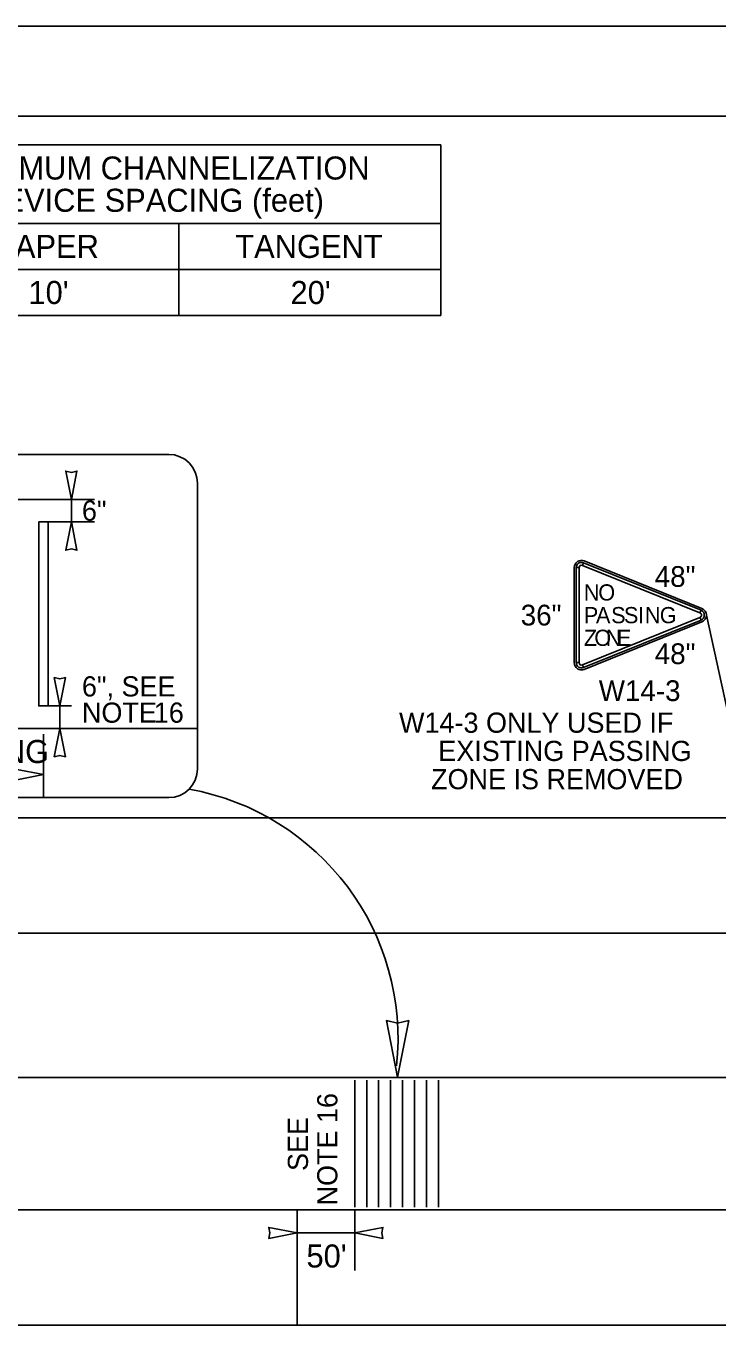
# Model space of a CAD drawing. Extents: x 99977 to 100176, y 99905 to 100011.
# Drawn here: x 100003.968 to 100006.368, y 99916.159 to 99920.687 of the extents above; entities that cross this region are included whole.
import ezdxf

# ---------------------------------------------------------------- set-up
doc = ezdxf.new("R2010")
doc.units = 0
for name, color, linetype in [('Default', 7, 'Continuous'), ('RD_ED_ShoulderPavedEdge', 7, 'Continuous'), ('RD_MK_LineEdgeWhite', 7, 'Continuous'), ('RD_MK_LineSkipCenter', 7, 'Continuous'), ('SH_GI_PlotLimits', 7, 'Continuous'), ('SH_GI_SheetBorder', 7, 'Continuous'), ('SH_TI_Tables', 7, 'Continuous'), ('TR_SN_ConstructionSigns', 7, 'Continuous'), ('TR_WZ_WorkZoneDetails', 7, 'Continuous'), ('TR_WZ_WorkZoneTextCurrent', 7, 'Continuous')]:
    doc.layers.add(name, color=color, linetype=linetype)

msp = doc.modelspace()

# ---------------------------------------------------------------- linework, layer by layer
at = {"layer": 'Default'}
for p, q in [((100005.8762, 99918.8083), (100005.886, 99918.8083)), ((100005.886, 99918.8083), (100005.8762, 99918.8083)), ((100005.8762, 99918.8083), (100005.8762, 99918.8083)), ((100005.8762, 99918.8083), (100005.886, 99918.8083)), ((100005.8976, 99918.8161), (100005.9013, 99918.8253)), ((100005.9013, 99918.8253), (100005.8976, 99918.8161)), ((100005.8976, 99918.8161), (100005.9013, 99918.8253))]:
    msp.add_line(p, q, dxfattribs=at)
for radius in [0.0183, 0.0183, 0.00844, 0.00844]:
    msp.add_arc((100005.8945, 99918.8083), radius, 67.9757, 180, dxfattribs=at)
at = {"layer": 'RD_ED_ShoulderPavedEdge'}
for p, q in [((100000.1076, 99917.9393), (100015.45, 99917.9393)), ((100000.1076, 99916.1793), (100015.45, 99916.1793))]:
    msp.add_line(p, q, dxfattribs=at)
at = {"layer": 'RD_MK_LineEdgeWhite'}
for p, q in [((100000.1076, 99917.5393), (100010.4406, 99917.5393)), ((100000.1076, 99916.5793), (100011.1899, 99916.5793))]:
    msp.add_line(p, q, dxfattribs=at)
at = {"layer": 'RD_MK_LineSkipCenter'}
msp.add_lwpolyline([(100006.4076, 99917.0393), (100001.2576, 99917.0393)], dxfattribs=at)
at = {"layer": 'SH_GI_PlotLimits'}
msp.add_lwpolyline([(99999.0625, 99909.6875), (100016.0625, 99909.6875), (100016.0625, 99920.6875), (99999.0625, 99920.6875)], close=True, dxfattribs=at)
at = {"layer": 'SH_GI_SheetBorder'}
msp.add_line((100000, 99920.375), (100015.75, 99920.375), dxfattribs=at)
at = {"layer": 'SH_TI_Tables'}
for p, q in [((100003.5886, 99920.275), (100005.4067, 99920.275)), ((100005.4067, 99919.683), (100005.4067, 99920.275)), ((100003.5886, 99920.003), (100005.4067, 99920.003)), ((100004.4977, 99919.683), (100004.4977, 99920.003)), ((100003.5886, 99919.843), (100004.4977, 99919.843)), ((100004.4977, 99919.843), (100005.4067, 99919.843)), ((100003.5886, 99919.683), (100005.4067, 99919.683))]:
    msp.add_line(p, q, dxfattribs=at)
at = {"layer": 'TR_SN_ConstructionSigns'}
for p, q in [((100005.8691, 99918.8083), (100005.8691, 99918.4784)), ((100005.8762, 99918.8083), (100005.8762, 99918.4784)), ((100005.8762, 99918.8083), (100005.8762, 99918.4784)), ((100005.886, 99918.8083), (100005.8762, 99918.8083)), ((100005.886, 99918.4784), (100005.886, 99918.8083)), ((100005.886, 99918.4784), (100005.886, 99918.8083)), ((100005.9013, 99918.8253), (100005.8976, 99918.8161)), ((100005.8976, 99918.8161), (100006.3054, 99918.6512)), ((100005.8976, 99918.8161), (100006.3054, 99918.6512)), ((100006.3091, 99918.6603), (100005.9013, 99918.8253)), ((100006.3091, 99918.6603), (100005.9013, 99918.8253)), ((100006.3117, 99918.6668), (100005.9039, 99918.8318)), ((100006.3054, 99918.6355), (100005.8976, 99918.4706)), ((100006.3054, 99918.6355), (100005.8976, 99918.4706)), ((100005.9013, 99918.4615), (100006.3091, 99918.6264)), ((100005.9013, 99918.4615), (100006.3091, 99918.6264)), ((100006.3091, 99918.6603), (100006.3054, 99918.6512)), ((100006.3054, 99918.6512), (100006.3091, 99918.6603)), ((100006.3091, 99918.6603), (100006.3054, 99918.6512)), ((100006.3054, 99918.6512), (100006.3091, 99918.6603)), ((100006.3054, 99918.6355), (100006.3091, 99918.6264)), ((100006.3091, 99918.6264), (100006.3054, 99918.6355)), ((100006.3054, 99918.6355), (100006.3091, 99918.6264)), ((100006.3091, 99918.6264), (100006.3054, 99918.6355)), ((100006.3091, 99918.6603), (100006.3091, 99918.6603)), ((100005.9039, 99918.4549), (100006.3117, 99918.6199)), ((100005.886, 99918.4784), (100005.8762, 99918.4784)), ((100005.8762, 99918.4784), (100005.886, 99918.4784)), ((100005.886, 99918.4784), (100005.8762, 99918.4784)), ((100005.8762, 99918.4784), (100005.886, 99918.4784)), ((100005.9013, 99918.4615), (100005.8976, 99918.4706)), ((100005.8976, 99918.4706), (100005.9013, 99918.4615)), ((100005.9013, 99918.4615), (100005.8976, 99918.4706)), ((100005.8976, 99918.4706), (100005.9013, 99918.4615)), ((100005.9013, 99918.4615), (100005.9013, 99918.4615))]:
    msp.add_line(p, q, dxfattribs=at)
for centre, radius, start, end in [((100005.8945, 99918.8083), 0.0253, 67.9757, 180), ((100006.3022, 99918.6434), 0.00844, 292.0243, 67.9757), ((100006.3022, 99918.6434), 0.00844, 292.0243, 67.9757), ((100006.3022, 99918.6434), 0.0183, 292.0243, 67.9757), ((100006.3022, 99918.6434), 0.0183, 292.0243, 67.9757), ((100006.3022, 99918.6434), 0.0253, 292.0243, 67.9757), ((100005.8945, 99918.4784), 0.0253, 180, 292.0243), ((100005.8945, 99918.4784), 0.0183, 180, 292.0243), ((100005.8945, 99918.4784), 0.0183, 180, 292.0243), ((100005.8945, 99918.4784), 0.00844, 180, 292.0243), ((100005.8945, 99918.4784), 0.00844, 180, 292.0243)]:
    msp.add_arc(centre, radius, start, end, dxfattribs=at)
at = {"layer": 'TR_WZ_WorkZoneDetails'}
for p, q in [((100002.7336, 99919.2011), (100004.4624, 99919.2011)), ((100004.4624, 99919.2011), (100002.7336, 99919.2011)), ((100004.5624, 99919.1011), (100004.5624, 99918.11)), ((100004.5624, 99918.11), (100004.5624, 99919.1011)), ((100003.3005, 99919.045), (100004.2047, 99919.045)), ((100004.1247, 99919.045), (100004.1247, 99918.967)), ((100004.0447, 99918.967), (100004.2047, 99918.967)), ((100006.3276, 99918.6434), (100006.4076, 99918.2793)), ((100004.0447, 99918.328), (100004.1247, 99918.328)), ((100004.0847, 99918.328), (100004.0847, 99918.25)), ((100002.6336, 99918.25), (100004.5624, 99918.25)), ((100004.028, 99918.25), (100004.1247, 99918.25)), ((100004.028, 99918.23), (100004.028, 99918.01)), ((100004.4624, 99918.01), (100002.7336, 99918.01)), ((100002.7336, 99918.01), (100004.4624, 99918.01)), ((100005.1076, 99916.5893), (100005.1076, 99917.0293)), ((100005.1493, 99916.5893), (100005.1493, 99917.0293)), ((100005.1904, 99916.5893), (100005.1904, 99917.0293)), ((100005.2322, 99916.5893), (100005.2322, 99917.0293)), ((100005.2739, 99916.5893), (100005.2739, 99917.0293)), ((100005.3151, 99916.5893), (100005.3151, 99917.0293)), ((100005.3568, 99916.5893), (100005.3568, 99917.0293)), ((100005.3985, 99916.5893), (100005.3985, 99917.0293)), ((100004.9076, 99916.1793), (100004.9076, 99916.5793)), ((100005.1076, 99916.5793), (100005.1076, 99916.3693)), ((100005.1076, 99916.4993), (100004.9076, 99916.4993))]:
    msp.add_line(p, q, dxfattribs=at)
for points in [[(100004.1247, 99919.045), (100004.1054, 99919.1433), (100004.1247, 99919.1388), (100004.144, 99919.1433)], [(100004.0114, 99918.967), (100004.0447, 99918.967), (100004.0447, 99918.328), (100004.0114, 99918.328)], [(100004.1247, 99918.967), (100004.1054, 99918.8687), (100004.1247, 99918.8733), (100004.144, 99918.8687)], [(100004.0847, 99918.328), (100004.0654, 99918.4263), (100004.0847, 99918.4218), (100004.104, 99918.4263)], [(100004.0847, 99918.25), (100004.0654, 99918.1517), (100004.0847, 99918.1563), (100004.104, 99918.1517)], [(100004.028, 99918.09), (100003.9298, 99918.1093), (100003.9343, 99918.09), (100003.9298, 99918.0707)], [(100005.2564, 99917.0395), (100005.2178, 99917.2361), (100005.2564, 99917.227), (100005.2949, 99917.2361)], [(100004.9076, 99916.4993), (100004.8093, 99916.48), (100004.8138, 99916.4993), (100004.8093, 99916.5186)], [(100005.1076, 99916.4993), (100005.2058, 99916.48), (100005.2013, 99916.4993), (100005.2058, 99916.5186)]]:
    msp.add_lwpolyline(points, close=True, dxfattribs=at)
for centre, radius, start, end in [((100004.4624, 99919.1011), 0.1, 0, 90), ((100004.4624, 99919.1011), 0.1, 0, 90), ((100004.4624, 99918.11), 0.1, 270, 0), ((100004.4624, 99918.11), 0.1, 270, 360), ((100004.378, 99917.173), 0.8801, 353.886, 79.846)]:
    msp.add_arc(centre, radius, start, end, dxfattribs=at)

# ---------------------------------------------------------------- texts
at = {"layer": 'SH_TI_Tables'}
for s, p in [('MAXIMUM CHANNELIZATION', (100003.6795, 99920.155)), ('DEVICE SPACING (feet)', (100003.8121, 99920.043)), ('TAPER', (100003.8636, 99919.883)), ('TANGENT', (100004.6934, 99919.883)), ("10'", (100003.9759, 99919.723)), ("20'", (100004.885, 99919.723))]:
    msp.add_text(s, height=0.08, rotation=360, dxfattribs=at).set_placement(p)
at = {"layer": 'TR_SN_ConstructionSigns'}
for s, height, p in [('48"', 0.072, (100006.1485, 99918.7414)), ('N', 0.0562, (100005.9025, 99918.694)), ('O', 0.0562, (100005.9526, 99918.694)), ('36"', 0.072, (100005.6836, 99918.6074)), ('P', 0.0562, (100005.9025, 99918.6152)), ('A', 0.0562, (100005.9445, 99918.6152)), ('S', 0.0562, (100005.9972, 99918.6152)), ('S', 0.0562, (100006.0416, 99918.6152)), ('I', 0.0562, (100006.0903, 99918.6152)), ('N', 0.0562, (100006.1141, 99918.6152)), ('G', 0.0562, (100006.1659, 99918.6152)), ('Z', 0.0562, (100005.9025, 99918.5365)), ('O', 0.0562, (100005.9389, 99918.5365)), ('N', 0.0562, (100005.9786, 99918.5365)), ('E', 0.0562, (100006.0173, 99918.5365))]:
    msp.add_text(s, height=height, dxfattribs=at).set_placement(p)
for s, p in [('48"', (100006.1485, 99918.4733)), ('W14-3', (100005.9543, 99918.3451))]:
    msp.add_text(s, height=0.072, rotation=360, dxfattribs=at).set_placement(p)
at = {"layer": 'TR_WZ_WorkZoneDetails'}
for s, rotation, p in [('6"', 360, (100004.1614, 99918.971)), ('6", SEE', 360, (100004.1614, 99918.3611)), ('NOTE', 360, (100004.1614, 99918.27)), ('16', 360, (100004.4107, 99918.27)), ('NOTE 16', 90, (100005.0476, 99916.5947)), ('SEE', 90, (100004.9456, 99916.7143))]:
    msp.add_text(s, height=0.07, rotation=rotation, dxfattribs=at).set_placement(p)
msp.add_text("4' SPACING", height=0.08, dxfattribs=at).set_placement((100003.4564, 99918.13))
at = {"layer": 'TR_WZ_WorkZoneTextCurrent'}
for s, p in [('W14-3 ONLY USED IF ', (100005.2614, 99918.2351)), ('EXISTING PASSING', (100005.3975, 99918.1371)), ('ZONE IS REMOVED', (100005.3725, 99918.0391))]:
    msp.add_text(s, height=0.07, rotation=360, dxfattribs=at).set_placement(p)
msp.add_text("50'", height=0.08, dxfattribs=at).set_placement((100004.9403, 99916.3793))

doc.saveas('drawing.dxf')
